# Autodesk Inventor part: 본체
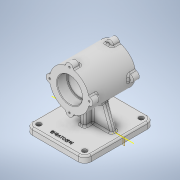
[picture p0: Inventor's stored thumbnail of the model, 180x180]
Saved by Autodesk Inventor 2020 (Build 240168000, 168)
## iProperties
Created: 2022-11
Part Number: 본체
Material: 일반
Document SubType Name: Modeling
Designer: owner
Density: 1 g/cm^3
Appearance: 기본값
Author: owner
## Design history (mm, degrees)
sketch "스케치1"
  geometry: L1 (65, -55)-(-65, -55); L2 (-65, -55)-(-65, 55); L3 (-65, 55)-(65, 55); L4 (65, 55)-(65, -55); L5 (65, -55)-(-65, 55); L6 (-65, -55)-(65, 55); 1 further point
  constraints: 12 end point, 2 midpoint, 2 parallel, 1 horizontal, 1 perpendicular
  dimensions: "d0" = 130 distance of L2.end L3.end; "d1" = 110 distance of L1.end L2.end
extrude "돌출1" new body sketch "스케치1" distance "d2" = 12; taper "d3" = 0 deg
node "작업 평면7"
sketch "스케치5"
  geometry: L1 (0, 0)-(110, 0) reference; C1 r 37 at (55, 82); 2 further points
  constraints: 1 centre point, 1 midpoint, 1 vertical alignment
  dimensions: "d11" = 74 diameter of C1; "d12" = 82 distance from line of L1 C1.centre
extrude "돌출2" join sketch "스케치5" stored distance "d13" = 87; taper "d14" = 0 deg
sketch "스케치7"
  geometry: C1 r 37 at (0, 0) reference; 2 further points
  constraints: 1 coincident
hole "구멍1" sketch "스케치7" at (0, 0) diameter "d17" = 42; stored, may be unused: countersink angle "d21" = 90 deg, drill point angle "d23" = 0 deg; dims "d18" = 12, "d19" = 47, "d20" = 19, "d22" = 43.5
sketch "스케치8"
  geometry: C1 r 37 at (0, 0) reference; A1 r 37 centre (0, 0) between (0, 37) and (-6.969, 36.338) reference; A2 r 7 centre (0, 37) between (6.969, 36.338) and (-6.969, 36.338); 3 further points
  constraints: 5 point on circle, 1 centre point, 1 vertical alignment
  dimensions: "d24" = 14 diameter of A2
extrude "돌출3" join sketch "스케치8" distance "d25" = 14; taper "d26" = 0 deg
sketch "스케치9"
  geometry: A1 r 7 centre (55, 119) between (61.969, 118.338) and (48.031, 118.338) reference; 2 further points
  constraints: 1 coincident
hole "구멍2" sketch "스케치9" at (55, 119) diameter "d27" = 3.242; stored, may be unused: countersink angle "d31" = 90 deg, drill point angle "d33" = 118 deg; dims "d28" = 8, "d29" = 47, "d30" = 19, "d32" = 10
sketch "스케치10"
  geometry: L1 (0, 12)-(110, 12) reference; L2 (96, 12)-(80.336, 55.036); L3 (110, 0)-(110, 12) reference; L4 (55, 45)-(55, 12); A1 r 37 centre (55, 82) between (61.969, 45.662) and (91.338, 75.031) reference; A2 r 37 centre (55, 82) between (91.338, 88.969) and (61.969, 118.338) reference; A3 r 37 centre (55, 82) between (61.969, 118.338) and (48.031, 118.338) reference; A4 r 37 centre (55, 82) between (48.031, 118.338) and (18.662, 88.969) reference; A5 r 37 centre (55, 82) between (18.662, 88.969) and (18.662, 75.031) reference; A6 r 37 centre (55, 82) between (18.662, 75.031) and (48.031, 45.662) reference; A7 r 37 centre (55, 82) between (48.031, 45.662) and (61.969, 45.662) reference; A8 r 37 centre (55, 82) between (61.969, 45.662) and (91.338, 75.031) reference; A9 r 37 centre (55, 82) between (91.338, 75.031) and (91.338, 88.969) reference; A10 r 37 centre (55, 82) between (91.338, 75.031) and (91.338, 88.969) reference; A11 r 37 centre (55, 82) between (61.969, 45.662) and (91.338, 75.031) reference; A12 r 37 centre (55, 82) between (48.031, 45.662) and (61.969, 45.662) reference; A13 r 37 centre (55, 82) between (18.662, 75.031) and (48.031, 45.662) reference; A14 r 37 centre (55, 82) between (18.662, 88.969) and (18.662, 75.031) reference; A15 r 37 centre (55, 82) between (48.031, 118.338) and (18.662, 88.969) reference; A16 r 37 centre (55, 82) between (61.969, 118.338) and (48.031, 118.338) reference; A17 r 37 centre (55, 82) between (91.338, 88.969) and (61.969, 118.338) reference; 4 further points
  constraints: 4 end point, 2 point on circle, 1 midpoint, 1 point on line, 2 other
  dimensions: "d37" = 14 distance from line of L3 L2.start; "d38" = 110 deg angle of L1 L2
extrude "돌출4" join sketch "스케치10" stored distance "d39" = 10; taper "d40" = 0 deg
node "작업 평면9"
sketch "스케치18"
  geometry: L1 (99.5, 45)-(40.5, 45) reference; L2 (75, 55.036)-(75, 12) reference; L3 (0, 12)-(130, 12) reference; L4 (90, 12)-(90, 45); L5 (70, -25.2)-(70, 151.2) reference; 1 further point
  constraints: 2 end point, 2 point on line, 1 perpendicular
  dimensions: "d47" = 20 distance between parallel lines of L4 L5
feature "리브1" sketch "스케치18" dims "d48" = 1, "d49" = 10, "d50" = 0, "d51" = 0, "d52" = 1, "d53" = 1
sketch "스케치20"
  geometry: L1 (5, -77)-(5, 77) reference; L2 (10, -41)-(0, -41) reference; 3 further points
  constraints: 2 midpoint
fillet "모깎기3" dims "d61" = 12
sketch "스케치21"
  geometry: A1 r 12 centre (-53, -43) between (-65, -43) and (-53, -55) reference; 2 further points
  constraints: 1 coincident
hole "구멍3" sketch "스케치21" at (-53, -43) diameter "d62" = 9; stored, may be unused: countersink angle "d66" = 90 deg, drill point angle "d68" = 0 deg; dims "d63" = 8, "d64" = 47, "d65" = 19, "d67" = 10
fillet "모깎기4" dims "d69" = 3
fillet "모깎기5" dims "d70" = 3
fillet "모깎기6" dims "d71" = 3
fillet "모깎기7" dims "d72" = 3
fillet "모깎기8" dims "d73" = 3
fillet "모깎기9" dims "d74" = 3
fillet "모깎기10" dims "d75" = 3
fillet "모깎기11" dims "d76" = 3
chamfer "모따기1" distance "d77" = 1; stored, may be unused: second distance "d78" = 2, angle "d79" = 45 deg
chamfer "모따기2" distance "d80" = 1; stored, may be unused: second distance "d81" = 2, angle "d82" = 45 deg
fillet "모깎기13" dims "d84" = 1
sketch "스케치23"
  geometry: L1 (5, -77)-(5, 77) reference; 2 further points
  constraints: 1 horizontal alignment, 1 other
  dimensions: "d85" = 58 distance from line of L1 point (-53, 0)
feature "엠보싱1" sketch "스케치23" dims "d19" = 47, "d86" = 0.5, "d87" = 0
node "솔리드1"
mirror "미러1"
pattern_circular "원형 패턴1" dims angle "d35" = 360 deg
mirror "미러2"
mirror "미러3"
mirror "미러4"
mirror "미러5"
mirror "미러6"
node "투영된 루프1"
feature "A9D066F2-1C7D-4E18-AEED-F7BC21143FA4" dims "d17" = 42, "d18" = 12, "d19" = 47, "d20" = 19, "d21" = 90 deg, "d22" = 43.5, "d23" = 0
